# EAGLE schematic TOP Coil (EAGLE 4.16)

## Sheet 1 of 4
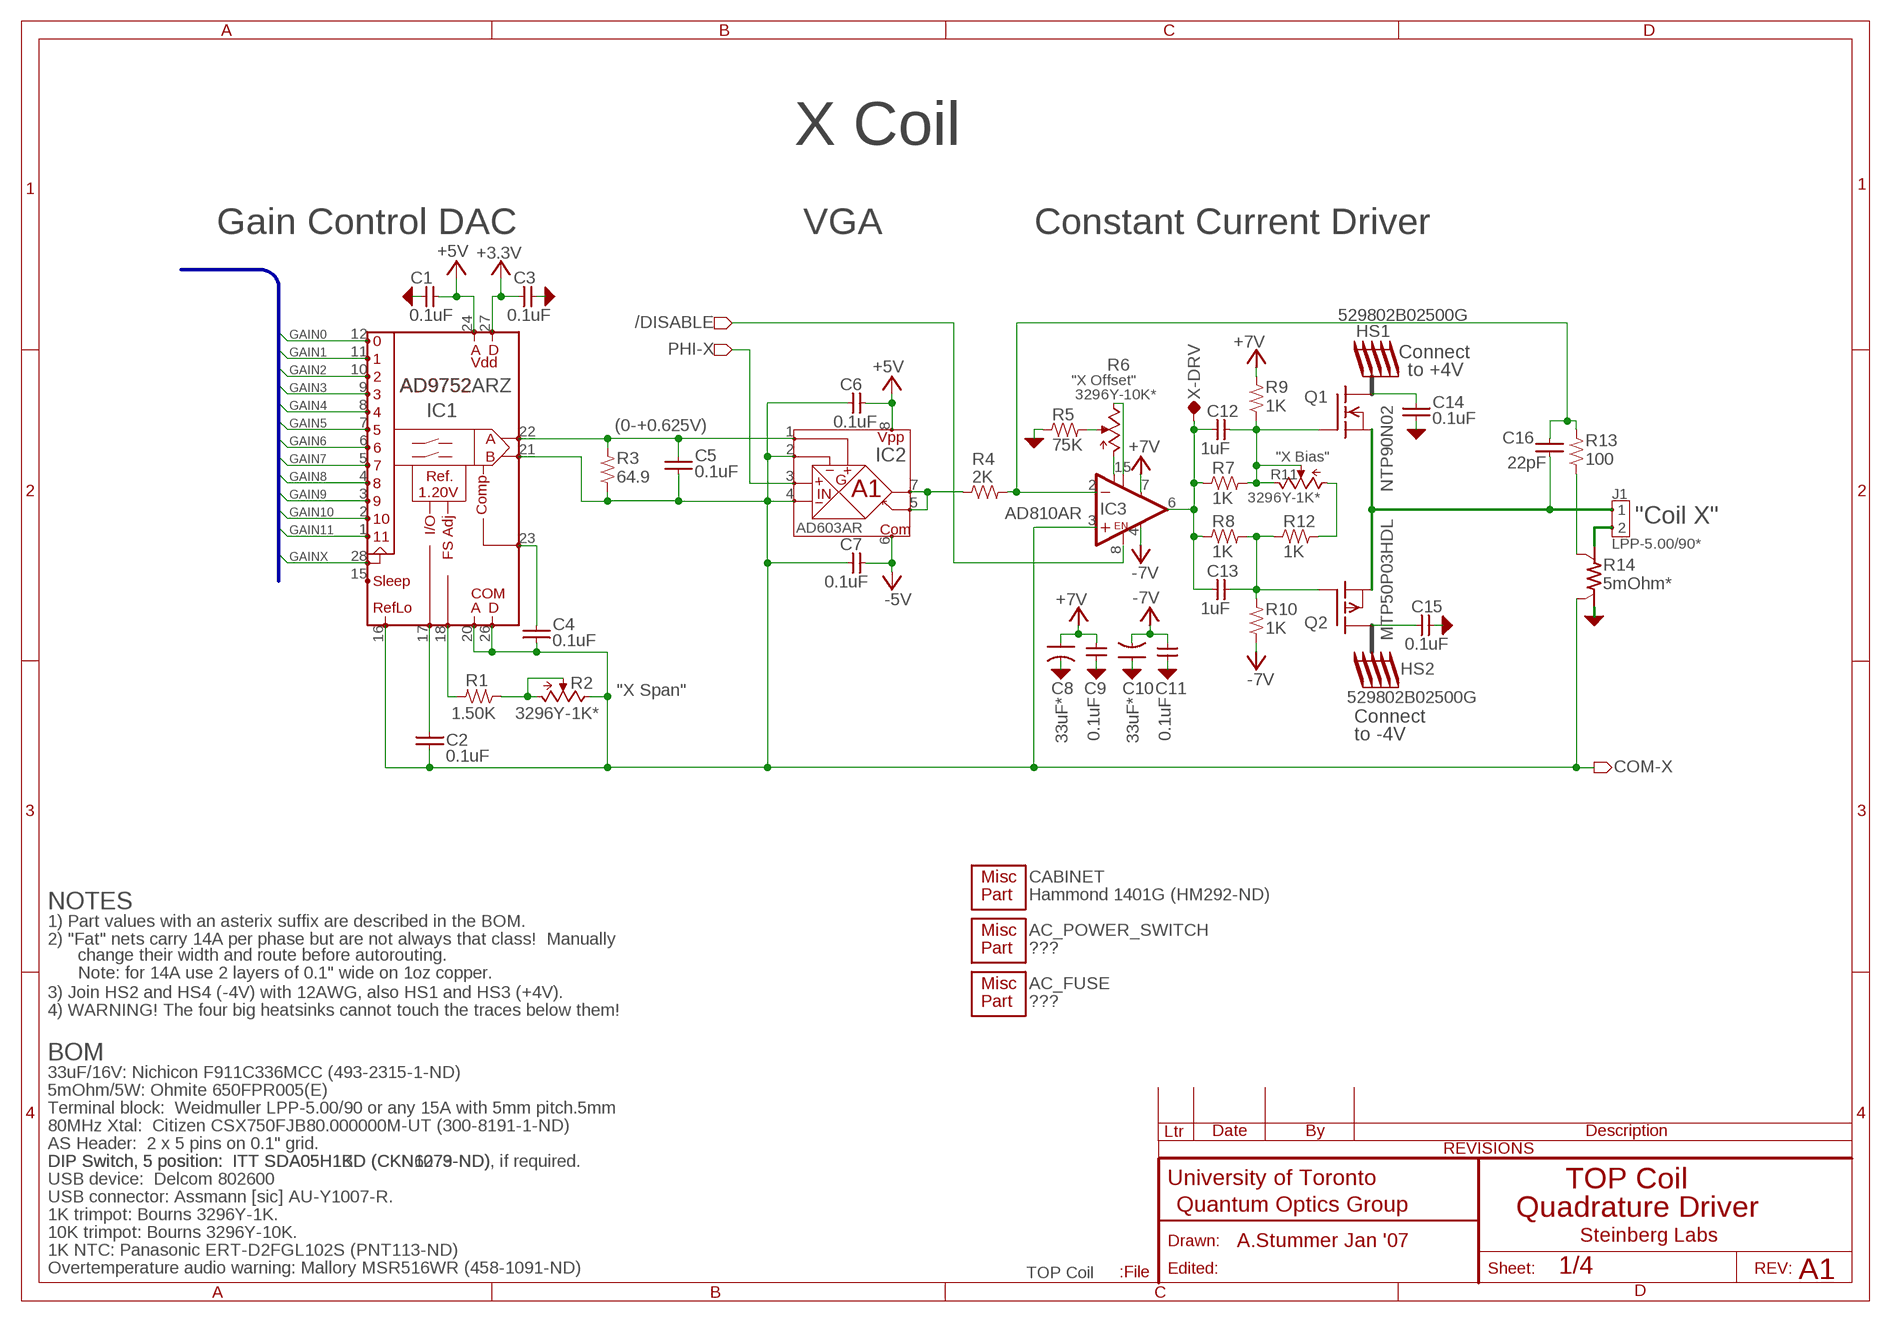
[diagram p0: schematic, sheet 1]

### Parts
C1  0.1uF  CAP-H-0603  [1608(0603)]
C2  0.1uF  CAP-V-0603  [1608(0603)]
C3  0.1uF  CAP-H-0603  [1608(0603)]
C4  0.1uF  CAP-V-0603  [1608(0603)]
C5  0.1uF  CAP-V-0603  [1608(0603)]
C6  0.1uF  CAP-H-0603  [1608(0603)]
C7  0.1uF  CAP-H-0603  [1608(0603)]
C8  33uF*  CAP-POL-6032  [EIA-6032]
C9  0.1uF  CAP-H-0603  [1608(0603)]
C10  33uF*  CAP-POL-6032  [EIA-6032]
C11  0.1uF  CAP-H-0603  [1608(0603)]
C12  1uF  CAP-H-0603  [1608(0603)]
C13  1uF  CAP-H-0603  [1608(0603)]
C14  0.1uF  CAP-V-0603  [1608(0603)]
C15  0.1uF  CAP-H-0603  [1608(0603)]
C16  22pF  CAP-V-0805  [2012(0805)]
HS1  529802B02500G  HEATSINK1529802...  [HEATSINK_529802B02(AAVID)]
HS2  529802B02500G  HEATSINK1529802...  [HEATSINK_529802B02(AAVID)]
IC1  AD9752ARZ  AD9752AR  [SOIC28]
IC2  AD603AR  AD603  [SOIC-8]
IC3  AD810AR  [SOIC-8]
J1  LPP-5.00/90*  CONN-2TERM-WEIDMULLER_5MM  [CONN-2TERM]
Q1  NTP90N02  MOSFET-N-TO220-VERT  [TO220-VERTICAL]
Q2  MTP50P03HDL  MOSFET-P-TO220-VERT  [TO220-VERTICAL]
R1  1.50K  R-V-0805  [2012(0805)]
R2  3296Y-1K*  POTBOURNS_3296Y  [BOURNS-3296Y]
R3  64.9  R-V-0805  [2012(0805)]
R4  2K  R-H-0805  [2012(0805)]
R5  75K  R-H-0805  [2012(0805)]
R6  3296Y-10K*  POTBOURNS_3296Y  [BOURNS-3296Y]
R7  1K  R-H-0805  [2012(0805)]
R8  1K  R-H-0805  [2012(0805)]
R9  1K  R-V-0805  [2012(0805)]
R10  1K  R-V-0805  [2012(0805)]
R11  3296Y-1K*  POTBOURNS_3296Y  [BOURNS-3296Y]
R12  1K  R-H-0805  [2012(0805)]
R13  100  R-V-0805  [2012(0805)]
R14  5mOhm*  R-SENSE-OHMITE_650  [OHMITE_650]
X-DRV  TP-0.042"  [TP-0.042]

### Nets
+3.3V: C3.1 IC1.27(DVDD) ; also sheet 2,3,4
+5V: C1.2 C6.2 IC1.24(AVDD) IC2.8(VPOS) ; also sheet 2,3,4
+7V: C8.+(POS) C9.1 IC3.7(V+) R9.2 ; also sheet 2,4
-5V: C7.2 IC2.6(VNEG) ; also sheet 2,3,4
-7V: C10.-(NEG) C11.2 IC3.4(V-) R10.1 ; also sheet 2,4
/DISABLE: IC3.8(/DISABLE) ; also sheet 2,3
AGND: C1.1 C3.2 C8.-(NEG) C9.2 C10.+(POS) C11.1 C14.1 C15.2 R5.1 R14.2A ; also sheet 2,3,4
COM-X: C2.1 C4.1 C5.1 C6.1 C7.1 IC1.16(REFLO) IC1.20(ACOM) IC1.21(IOUTB) IC1.26(DCOM) IC2.2(GNEG) IC2.4(COMM) IC3.3(+IN) R2.CW R3.1 R14.2B(2S) ; also sheet 3
GAIN0: IC1.12 ; also sheet 2,3
GAIN1: IC1.11 ; also sheet 2,3
GAIN2: IC1.10 ; also sheet 2,3
GAIN3: IC1.9 ; also sheet 2,3
GAIN4: IC1.8 ; also sheet 2,3
GAIN5: IC1.7 ; also sheet 2,3
GAIN6: IC1.6 ; also sheet 2,3
GAIN7: IC1.5 ; also sheet 2,3
GAIN8: IC1.4 ; also sheet 2,3
GAIN9: IC1.3 ; also sheet 2,3
GAIN10: IC1.2 ; also sheet 2,3
GAIN11: IC1.1 ; also sheet 2,3
GAINX: IC1.28(CLK) ; also sheet 3
N$1: IC3.1(NULL1) R6.CCW
N$2: IC3.5(NULL2) R6.CW
N$3: C16.1 J1.1 Q1.3(S) Q2.3(S)
N$4: J1.2 R14.1A
N$5: C12.1 C13.1 IC3.6(OUT) R7.1 R8.1 X-DRV.TP
N$6: C12.2 Q1.1(G) R7.2 R9.1 R11.CW R11.W
N$7: C13.2 Q2.1(G) R8.2 R10.2 R12.1
N$8: R13.1 R14.1B(1S)
N$9: C16.2 IC3.2(-IN) R4.2 R13.2
N$10: IC2.5(FDBK) IC2.7(VOUT) R4.1
N$27: C5.2 IC1.22(IOUTA) IC2.1(GPOS) R3.2
N$28: C2.2 IC1.17(REF)
N$36: R11.CCW R12.2
N$37: R5.2 R6.W
N$43: C4.2 IC1.23(COMP)
N$50: IC1.18(FSADJ) R1.2
N$51: R1.1 R2.CCW R2.W
N$86: C15.1 Q2.2(D)
N$87: C14.2 Q1.2(D)
PHI-X: IC2.3(VINP) ; also sheet 3
Unconnected: IC1.15(SLEEP)

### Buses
PHI[0..11],FREQ[0..4],USB[0..10],GAIN[0..11],INH,GAINX,GAINY

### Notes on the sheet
- X Coil
- Gain Control DAC | VGA | Constant Current Driver
- Connect
- to +4V
- "X Offset"
- (0-+0.625V)
- "X Bias"
- "Coil X"
- "X Span"
- Connect
- to -4V
- NOTES
- 1) Part values with an asterix suffix are described in the BOM.
- 2) "Fat" nets carry 14A per phase but are not always that class!  Manually
- change their width and route before autorouting.
- Note: for 14A use 2 layers of 0.1" wide on 1oz copper.
- 3) Join HS2 and HS4 (-4V) with 12AWG, also HS1 and HS3 (+4V).
- 4) WARNING! The four big heatsinks cannot touch the traces below them!
- BOM
- 33uF/16V: Nichicon F911C336MCC (493-2315-1-ND)
- 5mOhm/5W: Ohmite 650FPR005(E)
- Terminal block:  Weidmuller LPP-5.00/90 or any 15A with 5mm pitch.5mm
- 80MHz Xtal:  Citizen CSX750FJB80.000000M-UT (300-8191-1-ND)
- AS Header:  2 x 5 pins on 0.1" grid.
- DIP Switch, 5 position:  ITT	SDA05H1KD (CKN1279-ND) | DIP Switch, 5 position:  ITT SDA05H1BD (CKN6073-ND), if required.
- USB device:  Delcom 802600 | TOP Coil
- USB connector: Assmann [sic] AU-Y1007-R.
- 1K trimpot: Bourns 3296Y-1K. | Quadrature Driver
- 10K trimpot: Bourns 3296Y-10K. | Steinberg Labs
- A.Stummer Jan '07
- 1K NTC: Panasonic ERT-D2FGL102S (PNT113-ND)
- Overtemperature audio warning: Mallory MSR516WR (458-1091-ND)
- A1

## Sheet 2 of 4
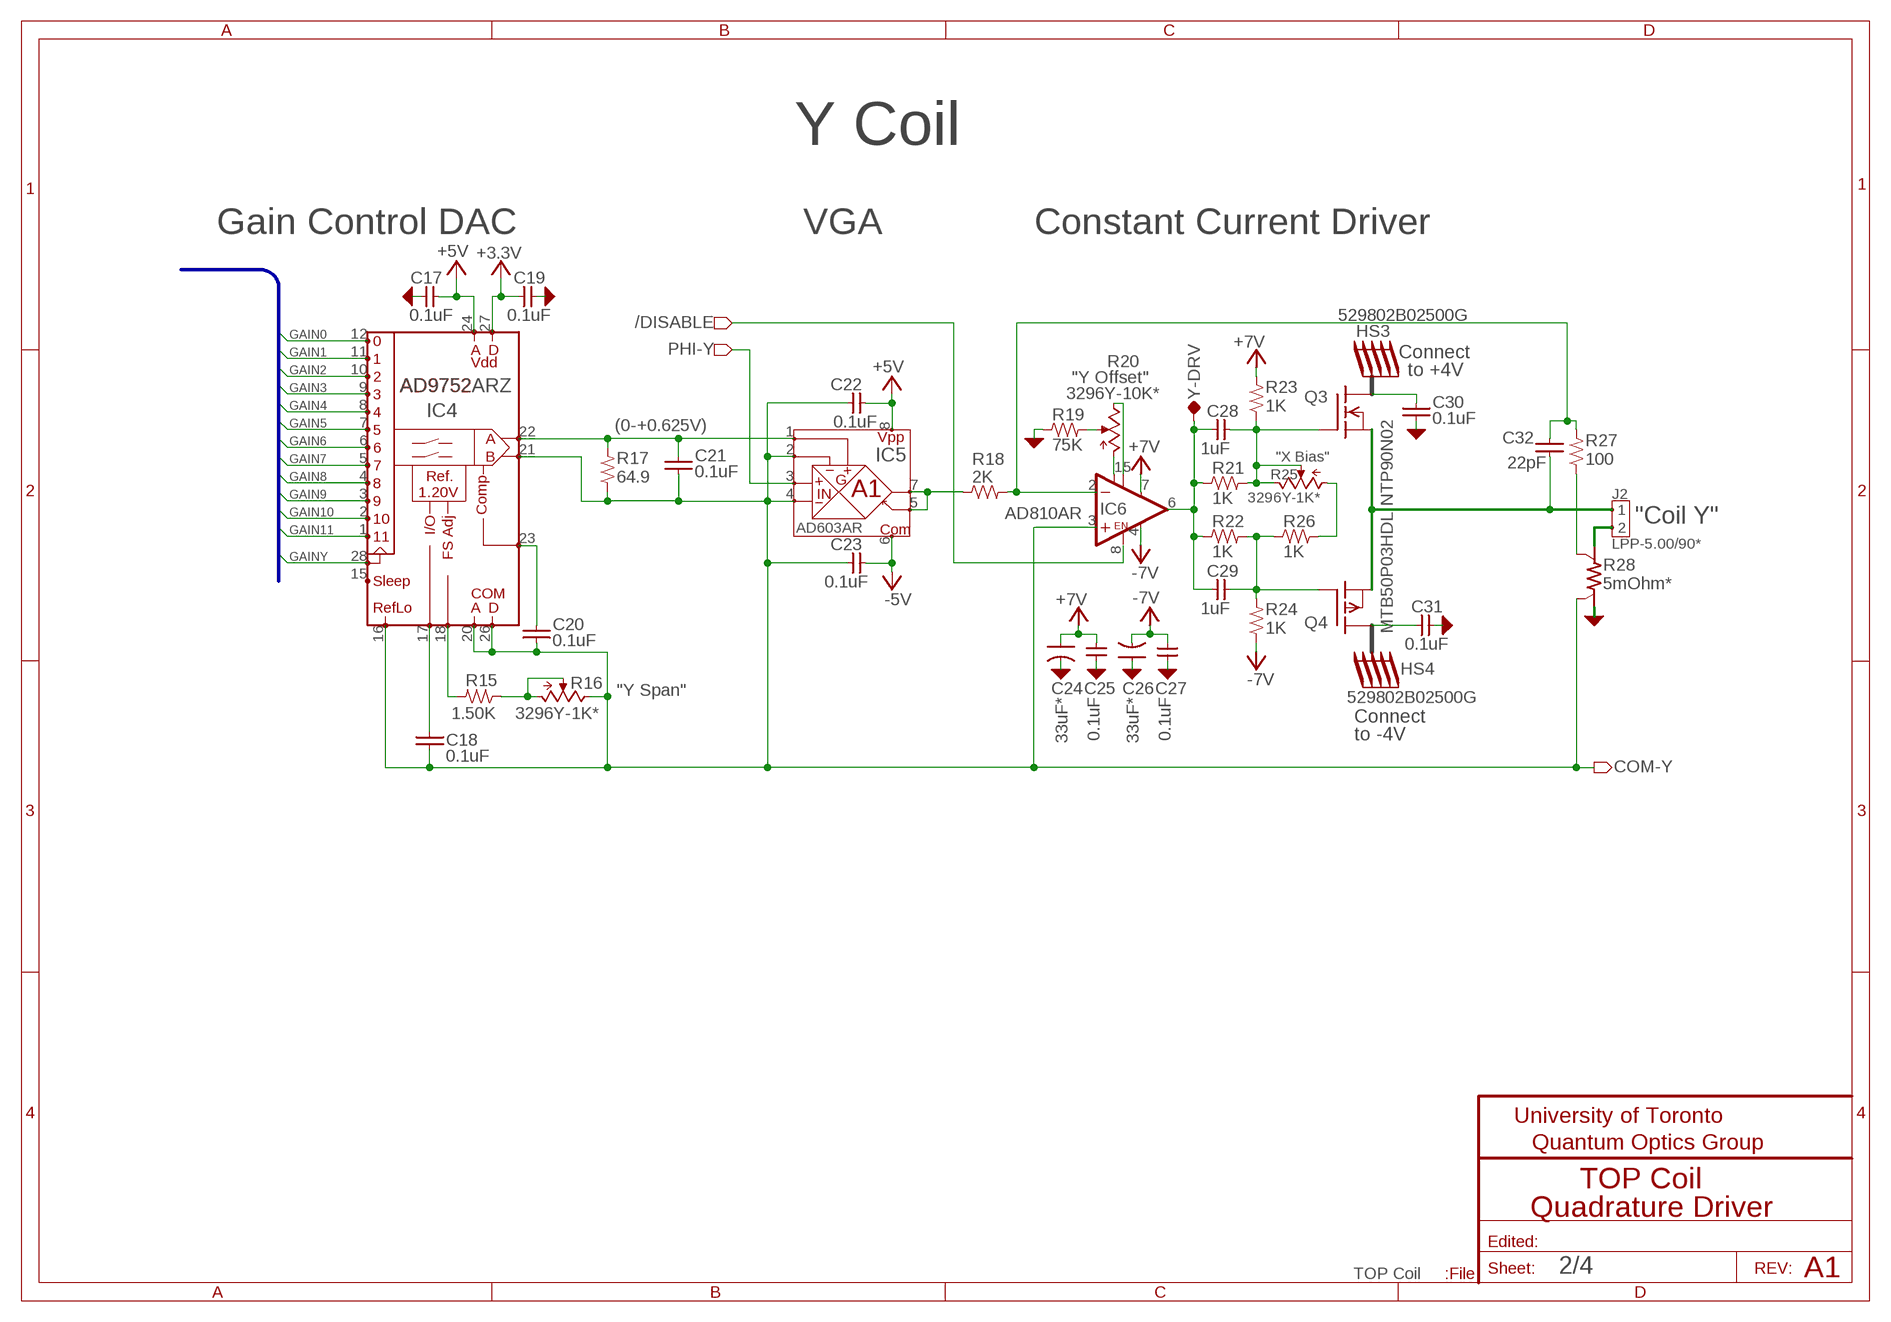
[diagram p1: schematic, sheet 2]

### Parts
C17  0.1uF  CAP-H-0603  [1608(0603)]
C18  0.1uF  CAP-V-0603  [1608(0603)]
C19  0.1uF  CAP-H-0603  [1608(0603)]
C20  0.1uF  CAP-V-0603  [1608(0603)]
C21  0.1uF  CAP-V-0603  [1608(0603)]
C22  0.1uF  CAP-H-0603  [1608(0603)]
C23  0.1uF  CAP-H-0603  [1608(0603)]
C24  33uF*  CAP-POL-6032  [EIA-6032]
C25  0.1uF  CAP-H-0603  [1608(0603)]
C26  33uF*  CAP-POL-6032  [EIA-6032]
C27  0.1uF  CAP-H-0603  [1608(0603)]
C28  1uF  CAP-H-0603  [1608(0603)]
C29  1uF  CAP-H-0603  [1608(0603)]
C30  0.1uF  CAP-V-0603  [1608(0603)]
C31  0.1uF  CAP-H-0603  [1608(0603)]
C32  22pF  CAP-V-0805  [2012(0805)]
HS3  529802B02500G  HEATSINK1529802...  [HEATSINK_529802B02(AAVID)]
HS4  529802B02500G  HEATSINK1529802...  [HEATSINK_529802B02(AAVID)]
IC4  AD9752ARZ  AD9752AR  [SOIC28]
IC5  AD603AR  AD603  [SOIC-8]
IC6  AD810AR  [SOIC-8]
J2  LPP-5.00/90*  CONN-2TERM-WEIDMULLER_5MM  [CONN-2TERM]
Q3  NTP90N02  MOSFET-N-TO220-VERT  [TO220-VERTICAL]
Q4  MTB50P03HDL  MOSFET-P-TO220-VERT  [TO220-VERTICAL]
R15  1.50K  R-V-0805  [2012(0805)]
R16  3296Y-1K*  POTBOURNS_3296Y  [BOURNS-3296Y]
R17  64.9  R-V-0805  [2012(0805)]
R18  2K  R-H-0805  [2012(0805)]
R19  75K  R-H-0805  [2012(0805)]
R20  3296Y-10K*  POTBOURNS_3296Y  [BOURNS-3296Y]
R21  1K  R-H-0805  [2012(0805)]
R22  1K  R-H-0805  [2012(0805)]
R23  1K  R-V-0805  [2012(0805)]
R24  1K  R-V-0805  [2012(0805)]
R25  3296Y-1K*  POTBOURNS_3296Y  [BOURNS-3296Y]
R26  1K  R-H-0805  [2012(0805)]
R27  100  R-V-0805  [2012(0805)]
R28  5mOhm*  R-SENSE-OHMITE_650  [OHMITE_650]
Y-DRV  TP-0.042"  [TP-0.042]

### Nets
+3.3V: C19.1 IC4.27(DVDD) ; also sheet 1,3,4
+5V: C17.2 C22.2 IC4.24(AVDD) IC5.8(VPOS) ; also sheet 1,3,4
+7V: C24.+(POS) C25.1 IC6.7(V+) R23.2 ; also sheet 1,4
-5V: C23.2 IC5.6(VNEG) ; also sheet 1,3,4
-7V: C26.-(NEG) C27.2 IC6.4(V-) R24.1 ; also sheet 1,4
/DISABLE: IC6.8(/DISABLE) ; also sheet 1,3
AGND: C17.1 C19.2 C24.-(NEG) C25.2 C26.+(POS) C27.1 C30.1 C31.2 R19.1 R28.2A ; also sheet 1,3,4
COM-Y: C18.1 C20.1 C21.1 C22.1 C23.1 IC4.16(REFLO) IC4.20(ACOM) IC4.21(IOUTB) IC4.26(DCOM) IC5.2(GNEG) IC5.4(COMM) IC6.3(+IN) R16.CW R17.1 R28.2B(2S) ; also sheet 3
GAIN0: IC4.12 ; also sheet 1,3
GAIN1: IC4.11 ; also sheet 1,3
GAIN2: IC4.10 ; also sheet 1,3
GAIN3: IC4.9 ; also sheet 1,3
GAIN4: IC4.8 ; also sheet 1,3
GAIN5: IC4.7 ; also sheet 1,3
GAIN6: IC4.6 ; also sheet 1,3
GAIN7: IC4.5 ; also sheet 1,3
GAIN8: IC4.4 ; also sheet 1,3
GAIN9: IC4.3 ; also sheet 1,3
GAIN10: IC4.2 ; also sheet 1,3
GAIN11: IC4.1 ; also sheet 1,3
GAINY: IC4.28(CLK) ; also sheet 3
N$11: C28.1 C29.1 IC6.6(OUT) R21.1 R22.1 Y-DRV.TP
N$12: C28.2 Q3.1(G) R21.2 R23.1 R25.CW R25.W
N$13: C29.2 Q4.1(G) R22.2 R24.2 R26.1
N$14: C32.1 J2.1 Q3.3(S) Q4.3(S)
N$15: J2.2 R28.1A
N$16: R27.1 R28.1B(1S)
N$17: C32.2 IC6.2(-IN) R18.2 R27.2
N$18: IC5.5(FDBK) IC5.7(VOUT) R18.1
N$19: C18.2 IC4.17(REF)
N$20: C20.2 IC4.23(COMP)
N$21: IC4.18(FSADJ) R15.2
N$22: R15.1 R16.CCW R16.W
N$23: C21.2 IC4.22(IOUTA) IC5.1(GPOS) R17.2
N$24: R25.CCW R26.2
N$25: IC6.1(NULL1) R20.CCW
N$26: IC6.5(NULL2) R20.CW
N$29: R19.2 R20.W
N$88: C31.1 Q4.2(D)
N$89: C30.2 Q3.2(D)
PHI-Y: IC5.3(VINP) ; also sheet 3
Unconnected: IC4.15(SLEEP)

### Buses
PHI[0..11],FREQ[0..4],USB[0..10],GAIN[0..11],INH,GAINX,GAINY

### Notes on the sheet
- Y Coil
- Gain Control DAC | VGA | Constant Current Driver
- Connect
- to +4V
- "Y Offset"
- (0-+0.625V)
- "X Bias"
- "Coil Y"
- "Y Span"
- Connect
- to -4V
- TOP Coil
- Quadrature Driver
- A1

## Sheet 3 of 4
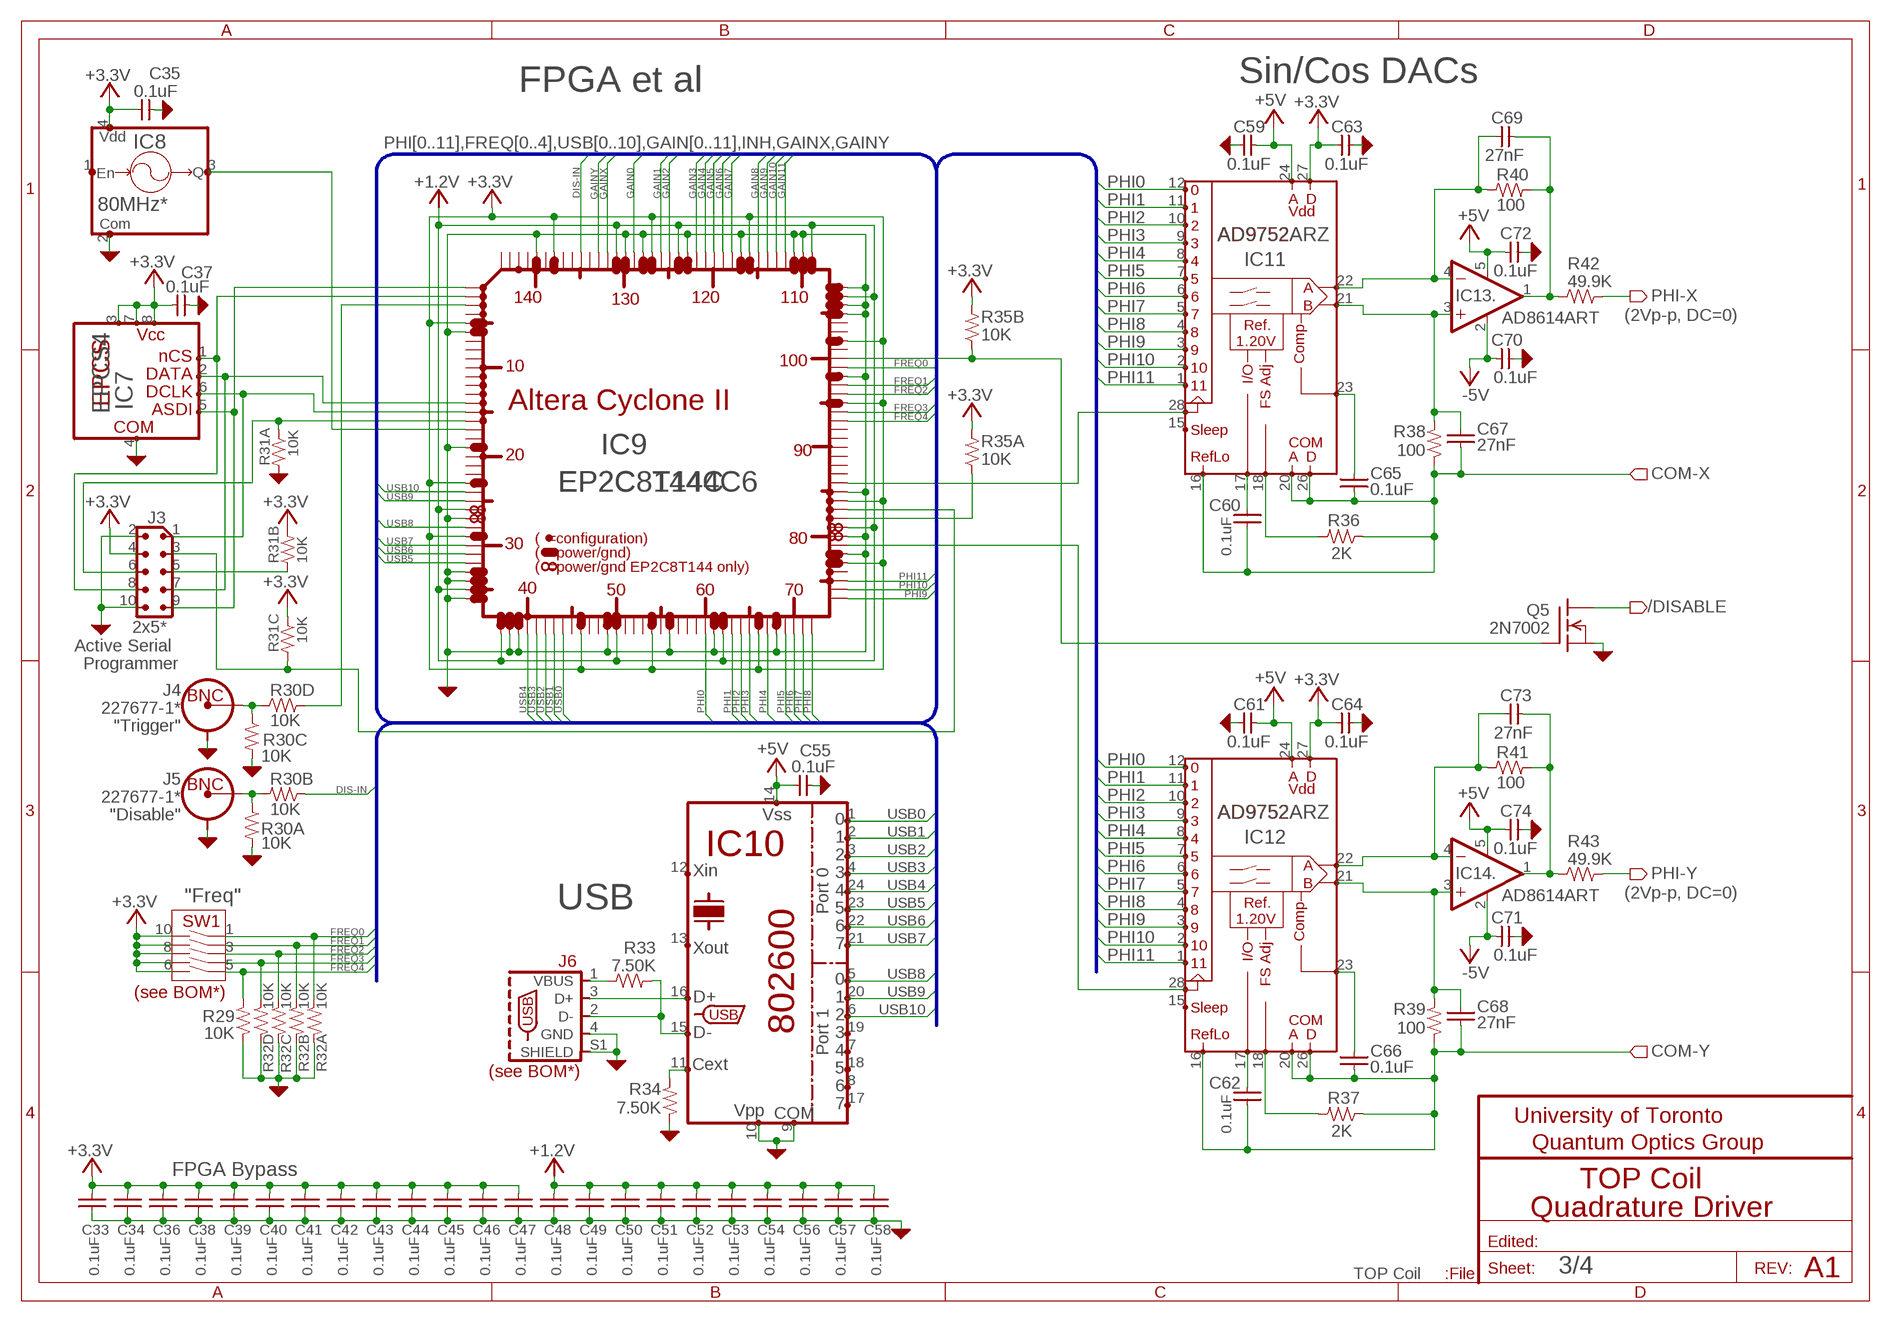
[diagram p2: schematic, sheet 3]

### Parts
C33  0.1uF  CAP-V-0603  [1608(0603)]
C34  0.1uF  CAP-V-0603  [1608(0603)]
C35  0.1uF  CAP-H-0603  [1608(0603)]
C36  0.1uF  CAP-V-0603  [1608(0603)]
C37  0.1uF  CAP-H-0603  [1608(0603)]
C38  0.1uF  CAP-V-0603  [1608(0603)]
C39  0.1uF  CAP-V-0603  [1608(0603)]
C40  0.1uF  CAP-V-0603  [1608(0603)]
C41  0.1uF  CAP-V-0603  [1608(0603)]
C42  0.1uF  CAP-V-0603  [1608(0603)]
C43  0.1uF  CAP-V-0603  [1608(0603)]
C44  0.1uF  CAP-V-0603  [1608(0603)]
C45  0.1uF  CAP-V-0603  [1608(0603)]
C46  0.1uF  CAP-V-0603  [1608(0603)]
C47  0.1uF  CAP-V-0603  [1608(0603)]
C48  0.1uF  CAP-V-0603  [1608(0603)]
C49  0.1uF  CAP-V-0603  [1608(0603)]
C50  0.1uF  CAP-V-0603  [1608(0603)]
C51  0.1uF  CAP-V-0603  [1608(0603)]
C52  0.1uF  CAP-V-0603  [1608(0603)]
C53  0.1uF  CAP-V-0603  [1608(0603)]
C54  0.1uF  CAP-V-0603  [1608(0603)]
C55  0.1uF  CAP-H-0603  [1608(0603)]
C56  0.1uF  CAP-V-0603  [1608(0603)]
C57  0.1uF  CAP-V-0603  [1608(0603)]
C58  0.1uF  CAP-V-0603  [1608(0603)]
C59  0.1uF  CAP-H-0603  [1608(0603)]
C60  0.1uF  CAP-V-0603  [1608(0603)]
C61  0.1uF  CAP-H-0603  [1608(0603)]
C62  0.1uF  CAP-V-0603  [1608(0603)]
C63  0.1uF  CAP-H-0603  [1608(0603)]
C64  0.1uF  CAP-H-0603  [1608(0603)]
C65  0.1uF  CAP-V-0603  [1608(0603)]
C66  0.1uF  CAP-V-0603  [1608(0603)]
C67  27nF  CAP-V-0805  [2012(0805)]
C68  27nF  CAP-V-0805  [2012(0805)]
C69  27nF  CAP-H-0805  [2012(0805)]
C70  0.1uF  CAP-H-0603  [1608(0603)]
C71  0.1uF  CAP-H-0603  [1608(0603)]
C72  0.1uF  CAP-H-0603  [1608(0603)]
C73  27nF  CAP-H-0805  [2012(0805)]
C74  0.1uF  CAP-H-0603  [1608(0603)]
IC7  EPCS4  EPCS1-4(ALTERA_CONFIG)  [SOIC-8]
IC8  80MHz*  CSX750(CITIZEN_OSC)  [CSX750(CITIZEN_OSC)]
IC9  EP2C8T144C6  ALTERA-EP2C_T144C_  [TQFP-144]
IC10  802600*  802600(DELCOM-USB)-SOIC24  [SOIC-24-0.3]
IC11  AD9752ARZ  AD9752AR  [SOIC28]
IC12  AD9752ARZ  AD9752AR  [SOIC28]
IC13  AD8614ART  OPAMPSOT23-5  [SOT23-5]
IC14  AD8614ART  OPAMPSOT23-5  [SOT23-5]
J3  2x5*  CONN-2X5-BLASTER  [CONN-2X5-BLASTER]
J4  227677-1*  CONN-BNCTYPE3HORIZ  [CONN-BNC-AMP-TYPE3HORIZ]
J5  227677-1*  CONN-BNCTYPE3HORIZ  [CONN-BNC-AMP-TYPE3HORIZ]
J6  (see BOM*)  AU-Y1007-USB-B  [CONN-USB_AU-Y1007]
Q5  2N7002  [SOT23]
R29  10K  R-V-0805  [2012(0805)]
R30  10K  R-4PAK-EXB-8V8  [PANASONIC_EXB-V8V(QUAD-R-PACK)]
R31  10K  R-4PAK-EXB-8V8  [PANASONIC_EXB-V8V(QUAD-R-PACK)]
R32  10K  R-4PAK-EXB-8V8  [PANASONIC_EXB-V8V(QUAD-R-PACK)]
R33  7.50K  R-H-0805  [2012(0805)]
R34  7.50K  R-V-0805  [2012(0805)]
R35  10K  R-4PAK-EXB-8V8  [PANASONIC_EXB-V8V(QUAD-R-PACK)]
R36  2K  R-V-0805  [2012(0805)]
R37  2K  R-V-0805  [2012(0805)]
R38  100  R-V-0805  [2012(0805)]
R39  100  R-V-0805  [2012(0805)]
R40  100  R-H-0805  [2012(0805)]
R41  100  R-H-0805  [2012(0805)]
R42  49.9K  R-H-0805  [2012(0805)]
R43  49.9K  R-H-0805  [2012(0805)]
SW1  (see BOM*)  SWITCH-5PST(DIP)-DIL10  [DIL10]

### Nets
+1.2V: C48.2 C49.2 C50.2 C51.2 C52.2 C53.2 C54.2 C56.2 C57.2 C58.2 IC9.26 IC9.35 IC9.37 IC9.50 IC9.62 IC9.81 IC9.107 IC9.109 IC9.124 IC9.131 ; also sheet 4
+3.3V: C33.2 C34.2 C35.1 C36.2 C37.1 C38.2 C39.2 C40.2 C41.2 C42.2 C43.2 C44.2 C45.2 C46.2 C47.2 C63.1 C64.1 IC7.3(VCC1) IC7.7(VCC2) IC7.8(VCC3) IC8.4(VDD) IC9.5 IC9.23 IC9.29 IC9.46 IC9.54 IC9.66 IC9.77 IC9.84 IC9.95 IC9.102 IC9.116 IC9.127 IC9.138 IC11.27(DVDD) IC12.27(DVDD) J3.4 R31.2B R31.3A R35.1B R35.2B SW1.6(5B) SW1.7(4B) SW1.8(3B) SW1.9(2B) SW1.10(1B) ; also sheet 1,2,4
+5V: C55.1 C59.2 C61.2 C72.2 C74.2 IC10.14(VCC) IC11.24(AVDD) IC12.24(AVDD) IC13.5(V+) IC14.5(V+) ; also sheet 1,2,4
-5V: C70.2 C71.2 IC13.2(V-) IC14.2(V-) ; also sheet 1,2,4
/DISABLE: Q5.3(D) ; also sheet 1,2
AGND: C33.1 C34.1 C35.2 C36.1 C37.2 C38.1 C39.1 C40.1 C41.1 C42.1 C43.1 C44.1 C45.1 C46.1 C47.1 C48.1 C49.1 C50.1 C51.1 C52.1 C53.1 C54.1 C55.2 C56.1 C57.1 C58.1 C59.1 C61.1 C63.2 C64.2 C70.1 C71.1 C72.1 C74.1 IC7.4(COM) IC8.2(COM) IC9.6 IC9.19 IC9.27 IC9.33 IC9.34 IC9.36 IC9.38 IC9.39 IC9.49 IC9.56 IC9.61 IC9.68 IC9.78 IC9.80 IC9.85 IC9.98 IC9.105 IC9.106 IC9.108 IC9.110 IC9.111 IC9.117 IC9.123 IC9.128 IC9.130 IC9.140 IC10.9(COM) IC10.10(VPP) J3.2 J3.10 J4.SHIELD J5.SHIELD J6.4(GND) J6.S1(SHIELD) Q5.2(S) R29.1 R30.1B R30.3B R31.1B R32.1A R32.2A R32.3A R32.4A R34.1 ; also sheet 1,2,4
COM-X: C60.1 C65.1 C67.1 IC11.16(REFLO) IC11.20(ACOM) IC11.26(DCOM) R36.1 R38.1 ; also sheet 1
COM-Y: C62.1 C66.1 C68.1 IC12.16(REFLO) IC12.20(ACOM) IC12.26(DCOM) R37.1 R39.1 ; also sheet 2
DIS-IN: IC9.135 R30.2A
FREQ0: IC9.99 R32.1B SW1.1(1A)
FREQ1: IC9.97 R32.2B SW1.2(2A)
FREQ2: IC9.96 R32.3B SW1.3(3A)
FREQ3: IC9.94 R32.4B SW1.4(4A)
FREQ4: IC9.93 R29.2 SW1.5(5A)
GAIN0: IC9.129 ; also sheet 1,2
GAIN1: IC9.126 ; also sheet 1,2
GAIN2: IC9.125 ; also sheet 1,2
GAIN3: IC9.122 ; also sheet 1,2
GAIN4: IC9.121 ; also sheet 1,2
GAIN5: IC9.120 ; also sheet 1,2
GAIN6: IC9.119 ; also sheet 1,2
GAIN7: IC9.118 ; also sheet 1,2
GAIN8: IC9.115 ; also sheet 1,2
GAIN9: IC9.114 ; also sheet 1,2
GAIN10: IC9.113 ; also sheet 1,2
GAIN11: IC9.112 ; also sheet 1,2
GAINX: IC9.132 ; also sheet 1
GAINY: IC9.133 ; also sheet 2
N$44: IC7.2(DATA) IC9.14 J3.7
N$48: IC7.6(DCLK) IC9.15 J3.1
N$49: IC7.5(ASDI) IC9.1 J3.9
N$52: IC7.1(NCS) IC9.2 J3.8
N$53: IC9.83 J3.3 R31.3B
N$54: J3.5 R31.2A
N$55: IC9.16 J3.6 R31.1A
N$56: IC9.82 R35.1A
N$57: IC8.3(Q) IC9.17
N$58: C60.2 IC11.17(REF)
N$59: C65.2 IC11.23(COMP)
N$60: C67.2 IC11.21(IOUTB) IC13.3(.:+IN) R38.2
N$61: C69.1 IC11.22(IOUTA) IC13.4(.:-IN) R40.1
N$62: C69.2 IC13.1(.:OUT) R40.2 R42.1
N$63: C66.2 IC12.23(COMP)
N$64: C68.2 IC12.21(IOUTB) IC14.3(.:+IN) R39.2
N$65: C73.1 IC12.22(IOUTA) IC14.4(.:-IN) R41.1
N$66: C73.2 IC14.1(.:OUT) R41.2 R43.1
N$67: IC9.3 R30.4B
N$68: J5.CONDUCTOR R30.1A R30.2B
N$69: IC11.18(FSADJ) R36.2
N$70: C62.2 IC12.17(REF)
N$71: IC12.18(FSADJ) R37.2
N$72: IC10.15(D-) J6.2(D-) R33.2
N$73: IC10.16(D+) J6.3(D+)
N$74: IC10.11(CEXT) R34.2
N$75: J6.1(VBUS) R33.1
N$76: IC9.86 IC11.28(CLK)
N$77: IC9.79 IC12.28(CLK)
N$78: J4.CONDUCTOR R30.3A R30.4A
N$79: IC9.100 Q5.1(G) R35.2A
PHI0: IC9.60 IC11.12 IC12.12
PHI1: IC9.63 IC11.11 IC12.11
PHI2: IC9.64 IC11.10 IC12.10
PHI3: IC9.65 IC11.9 IC12.9
PHI4: IC9.67 IC11.8 IC12.8
PHI5: IC9.69 IC11.7 IC12.7
PHI6: IC9.70 IC11.6 IC12.6
PHI7: IC9.71 IC11.5 IC12.5
PHI8: IC9.72 IC11.4 IC12.4
PHI9: IC9.73 IC11.3 IC12.3
PHI10: IC9.74 IC11.2 IC12.2
PHI11: IC9.75 IC11.1 IC12.1
PHI-X: R42.2 ; also sheet 1
PHI-Y: R43.2 ; also sheet 2
USB0: IC9.44 IC10.1(P0.0)
USB1: IC9.43 IC10.2(P0.1)
USB2: IC9.42 IC10.3(P0.2)
USB3: IC9.41 IC10.4(P0.3)
USB4: IC9.40 IC10.24(P0.4)
USB5: IC9.32 IC10.23(P0.5)
USB6: IC9.31 IC10.22(P0.6)
USB7: IC9.30 IC10.21(P0.7)
USB8: IC9.28 IC10.5(P1.0)
USB9: IC9.25 IC10.20(P1.1)
USB10: IC9.24 IC10.6(P1.2)
Unconnected: IC8.1(EN) IC9.4 IC9.7 IC9.8 IC9.9 IC9.10 IC9.11 IC9.12 IC9.13 IC9.18 IC9.20 IC9.21 IC9.22 IC9.45 IC9.47 IC9.48 IC9.51 IC9.52 IC9.53 IC9.55 IC9.57 IC9.58 IC9.59 IC9.76 IC9.87 IC9.88 IC9.89 IC9.90 IC9.91 IC9.92 IC9.101 IC9.103 IC9.104 IC9.134 IC9.136 IC9.137 IC9.139 IC9.141 IC9.142 IC9.143 IC9.144 IC10.7(P1.4) IC10.8(P1.6) IC10.12(XTL1) IC10.13(XTL2) IC10.17(P1.7) IC10.18(P1.5) IC10.19(P1.3) IC11.15(SLEEP) IC12.15(SLEEP) R31.4A R31.4B R35.3A R35.3B R35.4A R35.4B

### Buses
PHI[0..11],FREQ[0..4],USB[0..10],GAIN[0..11],INH,GAINX,GAINY

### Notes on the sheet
- FPGA et al | Sin/Cos DACs
- (2Vp-p, DC=0)
- Active Serial
- Programmer
- "Trigger"
- "Disable"
- "Freq" | (2Vp-p, DC=0)
- USB
- FPGA Bypass
- TOP Coil
- Quadrature Driver
- A1

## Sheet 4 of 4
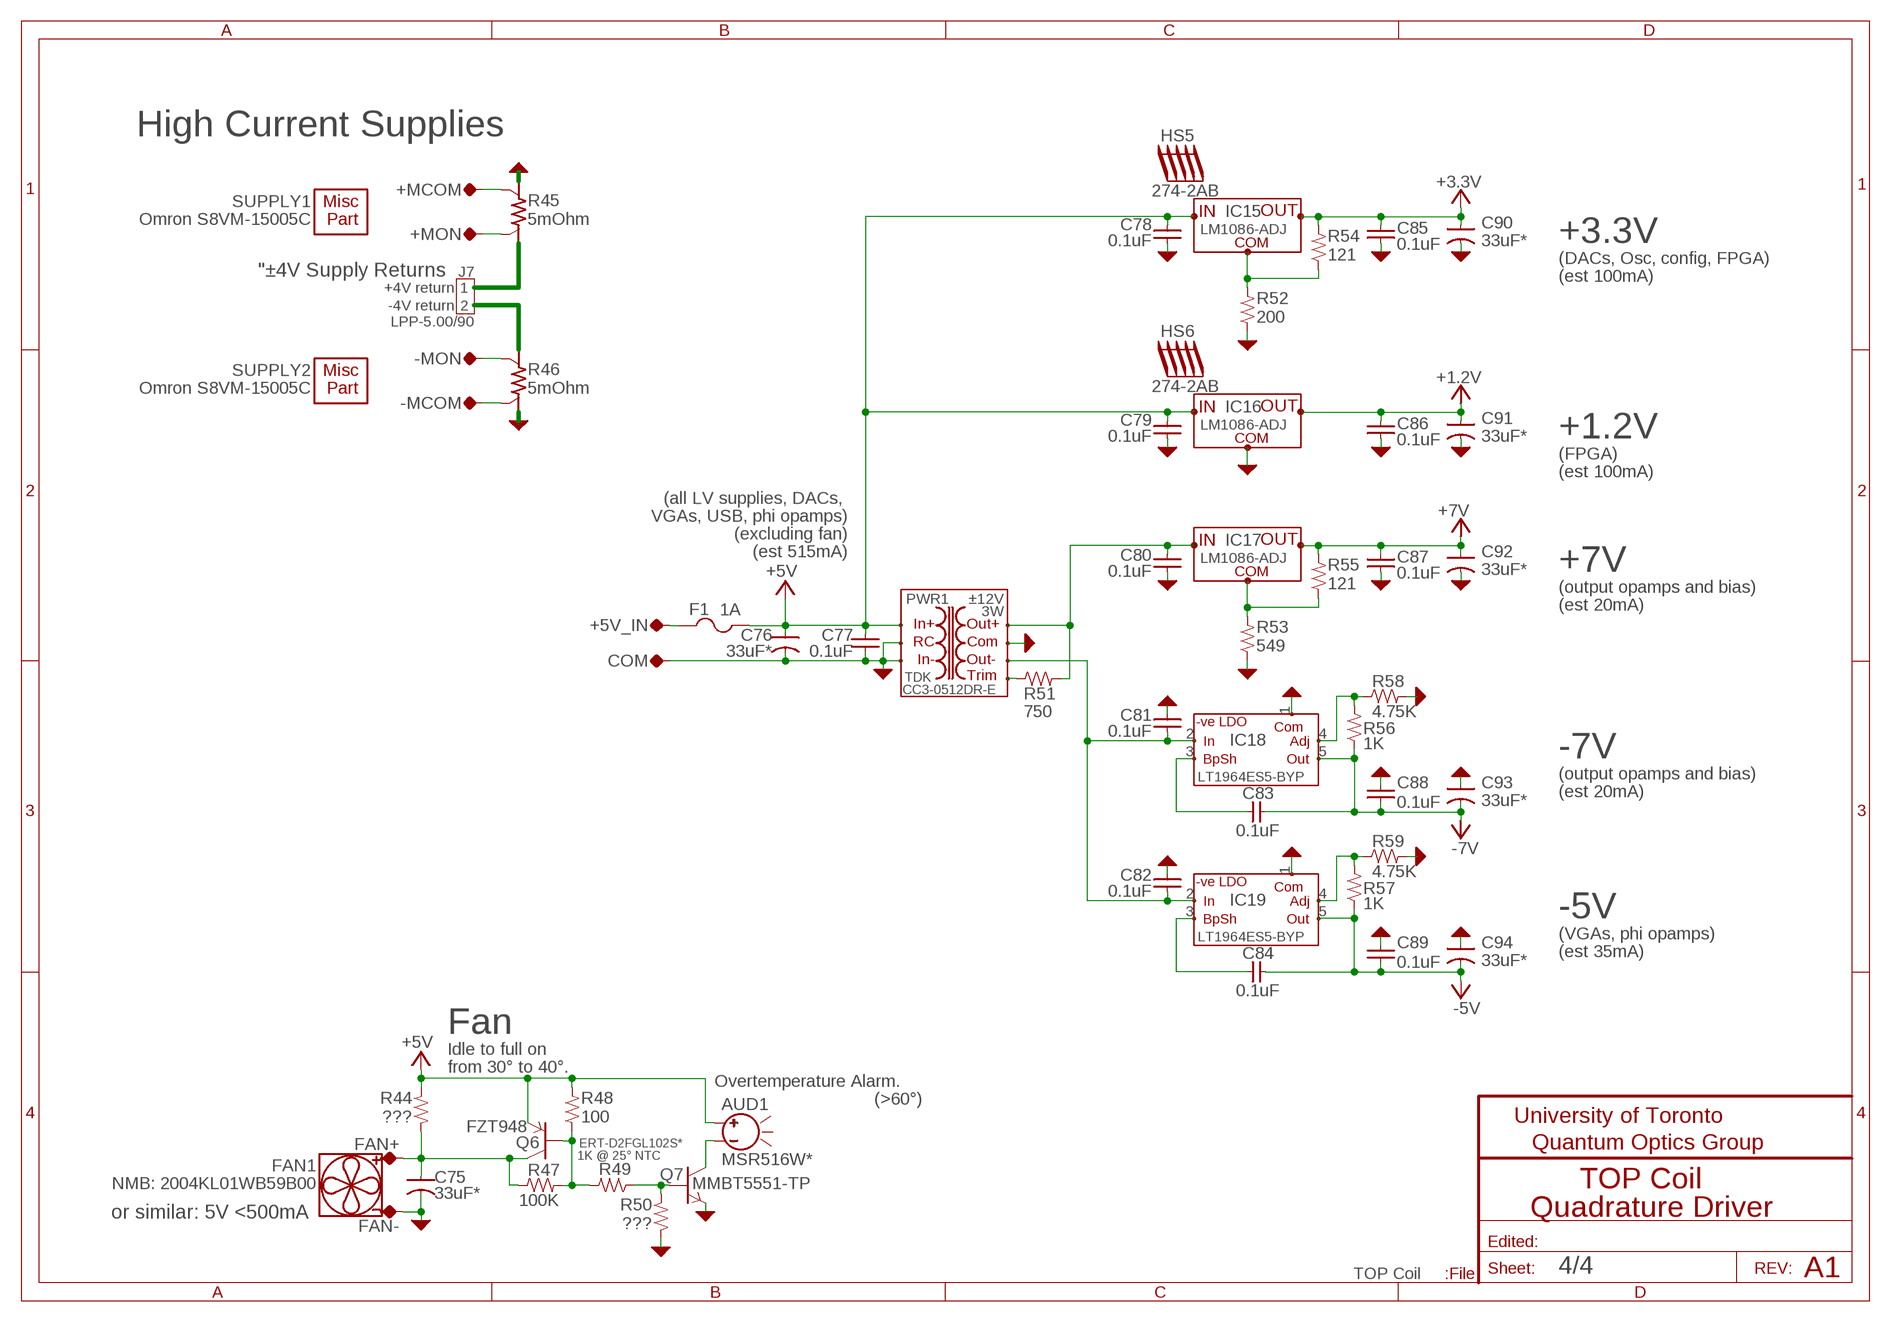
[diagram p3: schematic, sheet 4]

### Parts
+5V_IN  TP-0.042"  [TP-0.042]
+MCOM  TP-0.042"  [TP-0.042]
+MON  TP-0.042"  [TP-0.042]
-MCOM  TP-0.042"  [TP-0.042]
-MON  TP-0.042"  [TP-0.042]
AUD1  MSR516W*  AUDIO_DEVICE1  [AUDIO_DEVICE1]
C75  33uF*  CAP-POL-6032  [EIA-6032]
C76  33uF*  CAP-POL-6032  [EIA-6032]
C77  0.1uF  CAP-V-0603  [1608(0603)]
C78  0.1uF  CAP-V-0603  [1608(0603)]
C79  0.1uF  CAP-V-0603  [1608(0603)]
C80  0.1uF  CAP-V-0603  [1608(0603)]
C81  0.1uF  CAP-V-0603  [1608(0603)]
C82  0.1uF  CAP-V-0603  [1608(0603)]
C83  0.1uF  CAP-H-0603  [1608(0603)]
C84  0.1uF  CAP-H-0603  [1608(0603)]
C85  0.1uF  CAP-V-0603  [1608(0603)]
C86  0.1uF  CAP-V-0603  [1608(0603)]
C87  0.1uF  CAP-V-0603  [1608(0603)]
C88  0.1uF  CAP-V-0603  [1608(0603)]
C89  0.1uF  CAP-V-0603  [1608(0603)]
C90  33uF*  CAP-POL-6032  [EIA-6032]
C91  33uF*  CAP-POL-6032  [EIA-6032]
C92  33uF*  CAP-POL-6032  [EIA-6032]
C93  33uF*  CAP-POL-6032  [EIA-6032]
C94  33uF*  CAP-POL-6032  [EIA-6032]
COM  TP-0.042"  [TP-0.042]
F1  1A  FUSE-5X20-4  [FUSE]
FAN+  TP-0.042"  [TP-0.042]
FAN-  TP-0.042"  [TP-0.042]
HS5  274-2AB  HEATSINK1-274AB  [HEATSINK-3]
HS6  274-2AB  HEATSINK1-274AB  [HEATSINK-3]
IC15  LM1086-ADJ  LM1086-TO263  [TO263]
IC16  LM1086-ADJ  LM1086-TO263  [TO263]
IC17  LM1086-ADJ  LM1086-TO263  [TO263]
IC18  LT1964ES5-BYP  LT1964(NEG-LDO)-ES5-  [SOT23-5]
IC19  LT1964ES5-BYP  LT1964(NEG-LDO)-ES5-  [SOT23-5]
J7  LPP-5.00/90  CONN-2TERM-WEIDMULLER_5MM  [CONN-2TERM]
PWR1  CC3-0512DR-E  CC-E(TDK_DC-DC)CC3-X-E  [CC3-XXXXX-E(TDK_DC-DC)]
Q6  FZT948  BJT-PNP-SOT223  [SOT223]
Q7  MMBT5551-TP  BJT-NPN-SOT23  [SOT23]
R44  ???  R-V-THRU  [PASSIVE_0.4"]
R45  5mOhm  R-SENSE-OHMITE_650  [OHMITE_650]
R46  5mOhm  R-SENSE-OHMITE_650  [OHMITE_650]
R47  100K  R-H-0805  [2012(0805)]
R48  100  R-V-0805  [2012(0805)]
R49  ERT-D2FGL102S*  R-V-THRU  [PASSIVE_0.4"]
R50  ???  R-V-0805  [2012(0805)]
R51  750  R-H-0805  [2012(0805)]
R52  200  R-V-0805  [2012(0805)]
R53  549  R-V-0805  [2012(0805)]
R54  121  R-V-0805  [2012(0805)]
R55  121  R-V-0805  [2012(0805)]
R56  1K  R-V-0805  [2012(0805)]
R57  1K  R-V-0805  [2012(0805)]
R58  4.75K  R-H-0805  [2012(0805)]
R59  4.75K  R-H-0805  [2012(0805)]

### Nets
+1.2V: C86.2 C91.+(POS) IC16.2(OUT) ; also sheet 3
+3.3V: C85.2 C90.+(POS) IC15.2(OUT) R54.2 ; also sheet 1,2,3
+5V: AUD1.+ C76.+(POS) C77.2 C78.2 C79.2 F1.2A IC15.3(VI) IC16.3(VI) PWR1.+VIN(+IN) Q6.3(E) R44.2 R48.2 ; also sheet 1,2,3
+7V: C87.2 C92.+(POS) IC17.2(OUT) R55.2 ; also sheet 1,2
-5V: C84.2 C89.1 C94.-(NEG) IC19.5(OUT) R57.1 ; also sheet 1,2,3
-7V: C83.2 C88.1 C93.-(NEG) IC18.5(OUT) R56.1 ; also sheet 1,2
AGND: C75.-(NEG) C76.-(NEG) C77.1 C78.1 C79.1 C80.1 C81.2 C82.2 C85.1 C86.1 C87.1 C88.2 C89.2 C90.-(NEG) C91.-(NEG) C92.-(NEG) C93.+(POS) C94.+(POS) COM.TP FAN-.TP IC16.1(COM) IC18.1(COM) IC19.1(COM) PWR1.-VIN(-IN) PWR1.COM PWR1.RC Q7.2(E) R45.1A R46.2A R50.1 R52.1 R53.1 R58.2 R59.2 ; also sheet 1,2,3
N$30: -MCOM.TP R46.2B(2S)
N$31: -MON.TP R46.1B(1S)
N$32: +MON.TP R45.2B(2S)
N$33: +MCOM.TP R45.1B(1S)
N$34: J7.2 R46.1A
N$35: J7.1 R45.2A
N$38: +5V_IN.TP F1.1A
N$39: PWR1.TRM(TRIM) R51.1
N$40: C80.2 IC17.3(VI) PWR1.+VOUT(+OUT) R51.2
N$41: IC15.1(COM) R52.2 R54.1
N$42: Q7.1(B) R49.1 R50.2
N$45: IC19.4(ADJ) R57.2 R59.1
N$46: IC17.1(COM) R53.2 R55.1
N$47: IC18.4(ADJ) R56.2 R58.1
N$80: C83.1 IC18.3(BP/SH)
N$81: C84.1 IC19.3(BP/SH)
N$82: C81.1 C82.1 IC18.2(IN) IC19.2(IN) PWR1.-VOUT(-OUT)
N$83: C75.+(POS) FAN+.TP Q6.2(C) R44.1 R47.1
N$84: Q6.1(B) R47.2 R48.1 R49.2
N$85: AUD1.- Q7.3(C)

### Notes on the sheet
- High Current Supplies
- +3.3V
- (DACs, Osc, config, FPGA)
- "±4V Supply Returns
- (est 100mA)
- +4V return
- -4V return
- +1.2V
- (FPGA)
- (est 100mA)
- (all LV supplies, DACs,
- VGAs, USB, phi opamps)
- (excluding fan)
- (est 515mA)
- +7V
- (output opamps and bias)
- (est 20mA)
- ±12V
- 3W
- -7V
- (output opamps and bias)
- (est 20mA)
- -5V
- (VGAs, phi opamps)
- (est 35mA)
- Fan
- Idle to full on
- from 30° to 40°.
- Overtemperature Alarm.
- (>60°)
- 1K @ 25° NTC
- TOP Coil
- or similar: 5V <500mA | Quadrature Driver
- A1

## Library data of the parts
+5V_IN +MCOM +MON -MCOM -MON COM FAN+ FAN- X-DRV Y-DRV = QuantumOptics:TP: Testpoint, test point on schematic, on PCB either SMT pad, small hole or loop style TP.
AUD1 = QuantumOptics:AUDIO_DEVICE1: Audio Warning Device, Mallory MSR series, through hole, various sounds.
C1 C3 C6 C7 C9 C11-C13 C15 C17 C19 C22 C23 C25 C27-C29 C31 C35 C37 C55 C59 C61 C63 C64 C69-C74 C83 C84 = QuantumOptics:CAP-H-: Cap, SMT and Through-hole, 0402 and up.
C2 C4 C5 C14 C16 C18 C20 C21 C30 C32-C34 C36 C38-C54 C56-C58 C60 C62 C65-C68 C77-C82 C85-C89 = QuantumOptics:CAP-V-: Cap, SMT and Through-hole, 0402 and up.
C8 C10 C24 C26 C75 C76 C90-C94 = QuantumOptics:CAP-POL-: Capacitor, Polarized, SMT 0805 and up, probably tantalum.
F1 = QuantumOptics:FUSE: Fuse
HS1-HS6 = QuantumOptics:HEATSINK1: Heatsink, no connections to heatsink.
IC1 IC4 IC11 IC12 = QuantumOptics:AD9752: AD9752, Analog Device, 12-bit DAC, 145MHz, parallel. http://www.analog.com/UploadedFiles/Data_Sheets/70523322AD9752_0.pdf
IC2 IC5 = QuantumOptics:AD603: AD603, Analog Devices, variable gain amp, 90MHz, low noise. http://www.analog.com/UploadedFiles/Data_Sheets/AD603.pdf
IC3 IC6 = QuantumOptics:AD810: AD810, Analog Devices, 80MHz 1KV/uS 36V w/disable and trim. Bit heavy on Ib but not bad. http://www.analog.com/en/prod/0,2877,AD810,00.html
IC7 = QuantumOptics:EPCS1-4(ALTERA_CONFIG): EPCS1 or EPCS4, Altera, FPGA serial configuration device.
IC8 = QuantumOptics:CSX750(CITIZEN_OSC): CSX750 Oscillators, Citizen, +3.3V or +5V, 1MHZ to 133MHz. http://www.citizencrystal.com/images/pdf/os-csx750f.pdf
IC9 = QuantumOptics:ALTERA-EP2C_T144C_: Altera FPGA EP2C[5|8]T144Cx, Cyclone II, EP2C5T144Cx or EP2C8T144Cx, where x is speed grade. http://www.altera.com/literature/lit-cyc2.jsp
IC10 = QuantumOptics:802600(DELCOM-USB): 802600 USB Peripheral, Delcom, 16-bit USB to parallel interface, quick and dirty USB 1.1 peripheral solution.
IC13 IC14 = QuantumOptics:OPAMP: Op Amp, generic, pick the right package. e.g. AD8605: SOT-23-5, RRIO, 10MHz, Ib = 1pA, Vio < 65uV, 2.7-5.5V.
IC15-IC17 = QuantumOptics:LM1086: LM1086-xxx, National Semiconductor, LDO, adjustable or fixed. http://cache.national.com/ds/LM/LM1086.pdf
IC18 IC19 = QuantumOptics:LT1964(NEG-LDO): LT1964, LinTech, negative LDO, 200mA, fixed or -5V, very low noise. Three versions: 1) adj with shutdown, 2) adj with reference bypass, 3) fixed 5V with bypass and shutdown. http://www.linear.com/pc/downloadDocument.do?navId=H0,C1,C1003,C1040,C1019,P2168,D1258
J1 J2 J7 = QuantumOptics:CONN-2TERM: Connector, 2 Terminal, Weidmuller, 5mm pitch, up to 15A.
J3 = QuantumOptics:CONN-2X5-BLASTER: Connector, 2 rows of 5 for ByteBlaster, USBBlaster or MasterBlaster, on 0.1" grid, pins numbering zig-zags top-left to bottom-right.
J4 J5 = QuantumOptics:CONN-BNC: BNC PCB connectorsUses 0.1" grid.
J6 = QuantumOptics:AU-Y1007: USB Device side Connector, Assman [sic], PCB. Square USB-B type connector for load side.
PWR1 = QuantumOptics:CC-E(TDK_DC-DC): CCp-inoutsc-E, TDK DC-DC isolated, 1.5-25W, uni- or bipolar "p": 1.5, 3, 6, 10, 15, or 25W. "in": Input 05, 12, 24 or 48V. "out": Output 3.3, 5, 12, ±12 (or 24), ±15 (or30V). "s": Polarity single or dual. "c": Case horiz DIP, horiz SMD or vertical SIP. http://www.tdk.co.jp/tefe02/ea335_cc_e.pdf
Q1 Q3 = QuantumOptics:MOSFET-N: Mosfet, N-Channel, generic enhancement mode N-FET.
Q2 Q4 = QuantumOptics:MOSFET-P: MOSFET, P-channel, generic, in SOT-23 package. Warning! Check pinout! e.g. IR IRLML5103CT-ND (30V, 0.6?), http://www.irf.com/product-info/datasheets/data/irlml5103.pdf.
Q5 = QuantumOptics:2N7002: 2N7002, Zetex et al, NFET SOT-23, 60V 115mA (800p) 300mW Vth=TTL. General purpose small FET. http://www.zetex.com/3.0/pdf/2N7002.pdf
Q6 = QuantumOptics:BJT-PNP: PNP BJT, generic, p/n defined by VALUE field. E.g. Fairchild MMBT3906 (abs max 40V, 200mA. hFE>80@10mA.
Q7 = QuantumOptics:BJT-NPN: NPN BJT, generic, p/n defined by VALUE field. E.g. Fairchild MMBT5551 (abs max 160V, 600mA. hFE>80@10mA.
R1 R3 R9 R10 R13 R15 R17 R23 R24 R27 R29 R34 R36-R39 R44 R48-R50 R52-R57 = QuantumOptics:R-V-*: Resistor, SMT & Through-Hole, vertical symbol
R2 R6 R11 R16 R20 R25 = QuantumOptics:POT: Pot, regular or trimpot
R4 R5 R7 R8 R12 R18 R19 R21 R22 R26 R33 R40-R43 R47 R51 R58 R59 = QuantumOptics:R-H-*: Resistor, SMT & Through-Hole, horizontal symbol
R14 R28 R45 R46 = QuantumOptics:R-SENSE: Current sense resistor, 4-terminal. e.g. Ohmite series 60, http://www.ohmite.com/cgi-bin/showpage.cgi?product=60-4_series
R30-R32 R35 = QuantumOptics:R-4PAK: Quad Resistor Pack
SW1 = QuantumOptics:SWITCH-5PST(DIP): 5 position DIP switch, through-hole.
